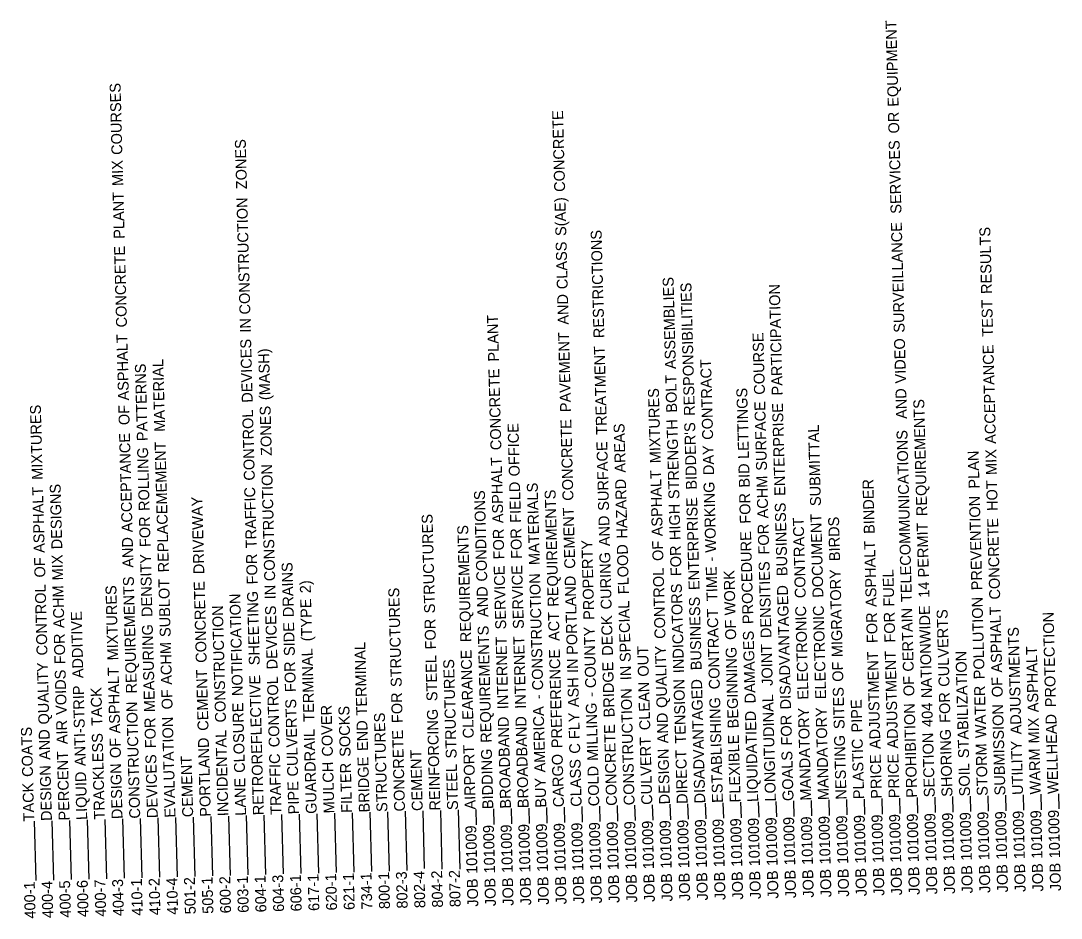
# Model space of a CAD drawing. Extents: x 1929542 to 1931706, y 595440 to 597808.
# Drawn here: x 1931132 to 1931706, y 596433 to 596929 of the extents above; entities that cross this region are included whole.
import ezdxf

# ---------------------------------------------------------------- set-up
doc = ezdxf.new("R2010")
doc.units = 0
doc.layers.add('Default', color=7, linetype='Continuous')

msp = doc.modelspace()

# ---------------------------------------------------------------- linework, layer by layer
at = {"layer": 'Default'}
for p, q in [((1931626.3, 596499.8), (1931626.52, 596491.27)), ((1931636.04, 596500.06), (1931636.27, 596491.53)), ((1931645.79, 596500.33), (1931646.02, 596491.79)), ((1931655.53, 596500.59), (1931655.76, 596492.05)), ((1931665.28, 596500.85), (1931665.51, 596492.31)), ((1931675.03, 596501.11), (1931675.26, 596492.57)), ((1931684.77, 596501.37), (1931685, 596492.84)), ((1931694.52, 596501.63), (1931694.75, 596493.1)), ((1931704.27, 596501.9), (1931704.49, 596493.63)), ((1931411.87, 596494.05), (1931412.1, 596485.51)), ((1931421.62, 596494.31), (1931421.85, 596485.77)), ((1931431.37, 596494.57), (1931431.59, 596486.03)), ((1931441.11, 596494.83), (1931441.34, 596486.29)), ((1931450.86, 596495.09), (1931451.09, 596486.56)), ((1931460.61, 596495.36), (1931460.83, 596486.82)), ((1931470.35, 596495.62), (1931470.58, 596487.08)), ((1931480.1, 596495.88), (1931480.33, 596487.34)), ((1931489.84, 596496.14), (1931490.07, 596487.6)), ((1931499.59, 596496.4), (1931499.82, 596487.86)), ((1931509.34, 596496.66), (1931509.57, 596488.13)), ((1931519.08, 596496.93), (1931519.31, 596488.39)), ((1931528.83, 596497.19), (1931529.06, 596488.65)), ((1931538.58, 596497.45), (1931538.81, 596488.91)), ((1931548.32, 596497.71), (1931548.55, 596489.17)), ((1931558.07, 596497.97), (1931558.3, 596489.43)), ((1931567.82, 596498.23), (1931568.05, 596489.7)), ((1931577.56, 596498.5), (1931577.79, 596489.96)), ((1931587.31, 596498.76), (1931587.54, 596490.22)), ((1931597.06, 596499.02), (1931597.29, 596490.48)), ((1931606.8, 596499.28), (1931607.03, 596490.74)), ((1931616.55, 596499.54), (1931616.78, 596491)), ((1931197.45, 596488.29), (1931198.33, 596455.55)), ((1931207.2, 596488.55), (1931208.08, 596455.81)), ((1931216.94, 596488.81), (1931217.82, 596456.07)), ((1931226.69, 596489.08), (1931227.57, 596456.33)), ((1931236.44, 596489.34), (1931237.31, 596456.59)), ((1931246.18, 596489.6), (1931247.06, 596456.86)), ((1931255.93, 596489.86), (1931256.81, 596457.12)), ((1931265.68, 596490.12), (1931266.55, 596457.38)), ((1931275.42, 596490.38), (1931276.3, 596457.64)), ((1931285.17, 596490.65), (1931286.05, 596457.9)), ((1931294.91, 596490.91), (1931295.79, 596458.16)), ((1931304.66, 596491.17), (1931305.54, 596458.43)), ((1931314.41, 596491.43), (1931315.29, 596458.69)), ((1931324.15, 596491.69), (1931325.03, 596458.95)), ((1931333.9, 596491.95), (1931334.78, 596459.21)), ((1931343.65, 596492.22), (1931344.53, 596459.47)), ((1931353.39, 596492.48), (1931354.25, 596460.68)), ((1931363.14, 596492.74), (1931364.01, 596460.25)), ((1931372.89, 596493), (1931373.77, 596460.26)), ((1931382.63, 596493.26), (1931382.86, 596484.72)), ((1931392.38, 596493.52), (1931392.61, 596484.99)), ((1931402.13, 596493.79), (1931402.36, 596485.25)), ((1931138.97, 596486.72), (1931139.85, 596453.98)), ((1931148.72, 596486.98), (1931149.6, 596454.24)), ((1931158.46, 596487.24), (1931159.34, 596454.5)), ((1931168.21, 596487.51), (1931169.09, 596454.76)), ((1931177.96, 596487.77), (1931178.84, 596455.02)), ((1931187.7, 596488.03), (1931188.58, 596455.29))]:
    msp.add_line(p, q, dxfattribs=at)

# ---------------------------------------------------------------- texts
for s, p in [(' EQUIPMENT', (1931616.12, 596879.03)), (' COURSES', (1931187.67, 596852.45)), (' CONCRETE', (1931432.06, 596832.02)), (' OR', (1931616.51, 596864.25)), (' ZONES', (1931256.46, 596833.49)), (' SERVICES', (1931617.7, 596819.97)), (' MIX', (1931188.14, 596835.28)), (' PLANT', (1931188.92, 596806.11)), (' CONSTRUCTION', (1931258.31, 596764.34)), (' S(AE)', (1931432.71, 596807.65)), (' SURVEILLANCE', (1931619.46, 596754.28)), (' RESTRICTIONS', (1931453.73, 596751.29)), (' RESULTS', (1931667.66, 596775.66)), (' CONCRETE', (1931190.23, 596757.2)), (' CLASS', (1931433.5, 596778.28)), (' ASSEMBLIES', (1931493.21, 596734.2)), (' RESPONSIBILITIES', (1931503.65, 596708.4)), (' PARTICIPATION', (1931552.12, 596719.63)), (' AND', (1931434.03, 596758.7)), (' TEST', (1931668.29, 596752.08)), (' IN', (1931258.58, 596754.32)), (' PLANT', (1931395.56, 596738.34)), (' ASPHALT', (1931191.31, 596716.85)), (' DEVICES', (1931259.62, 596715.64)), (' PAVEMENT', (1931435.32, 596710.43)), (' COURSE', (1931542.35, 596720.05)), (' VIDEO', (1931620.22, 596726.25)), (' (MASH)', (1931269.34, 596717.06)), (' TREATMENT', (1931455.17, 596697.91)), (' ACCEPTANCE', (1931669.88, 596692.91)), (' MATERIAL', (1931211.28, 596699.59)), (' CONTRACT', (1931513.76, 596695.15)), (' PATTERNS', (1931201.67, 596694.45)), (' CONCRETE', (1931396.87, 596689.43)), (' BOLT', (1931493.85, 596710.15)), (' MIXTURES', (1931484.85, 596682.22)), (' LETTINGS', (1931533.55, 596684.61)), (' AND', (1931620.74, 596706.67)), (' SURFACE', (1931543.48, 596678.12)), (' REQUIREMENTS', (1931631.94, 596653.01)), (' MIXTURES', (1931143.72, 596673.07)), (' OF', (1931191.68, 596703.27)), (' CONTROL', (1931260.78, 596672.63)), (' ZONES', (1931270.16, 596686.3)), (' ENTERPRISE', (1931553.61, 596664.19)), (' CONCRETE', (1931436.64, 596661.52)), (' STRENGTH', (1931495.13, 596662.4)), (" BIDDER'S", (1931504.75, 596667.65)), (' ACCEPTANCE', (1931193.27, 596644.1)), (' OFFICE', (1931407.02, 596674.97)), (' AREAS', (1931465.48, 596676.98)), (' SUBMITTAL', (1931573.27, 596658.57)), (' TELECOMMUNICATIONS', (1931623.46, 596605.61)), (' REPLACEMEMENT', (1931213.37, 596621.99)), (' SURFACE', (1931456.29, 596655.98)), (' ROLLING', (1931202.71, 596655.87)), (' DAY', (1931514.29, 596675.65)), (' PLAN', (1931660.79, 596668.23)), (' MIX', (1931670.34, 596675.74)), (' ASPHALT', (1931397.96, 596649.08)), (' BID', (1931533.98, 596668.76)), (' CONSTRUCTION', (1931272.02, 596617.14)), (' ASPHALT', (1931485.93, 596641.87)), (' DESIGNS', (1931154.5, 596634.73)), (' FIELD', (1931407.7, 596649.34)), (' MATERIALS', (1931418.08, 596626.01)), (' HAZARD', (1931466.46, 596640.64)), (' WORKING', (1931515.43, 596632.88)), (' ACHM', (1931544.19, 596651.75)), (' BINDER', (1931602.94, 596643.21)), (' HOT', (1931670.87, 596655.89)), (' ASPHALT', (1931144.81, 596632.71)), (' TRAFFIC', (1931261.78, 596635.25)), (' CONDITIONS', (1931389.07, 596616.9)), (' REQUIREMENTS', (1931428.45, 596603.02)), (' FOR', (1931534.51, 596648.86)), (' DRIVEWAY', (1931232.9, 596620.98)), (' HIGH', (1931495.74, 596639.8)), (' ENTERPRISE', (1931506.24, 596612.21)), (' BUSINESS', (1931554.8, 596619.92)), (' PREVENTION', (1931662.3, 596612.1)), (' FOR', (1931203.24, 596635.96)), (' STRUCTURES', (1931360.28, 596599.37)), (' CEMENT', (1931437.65, 596623.98)), (' AND', (1931456.82, 596636.41)), (' DOCUMENT', (1931574.62, 596607.99)), (' REQUIREMENTS', (1931380.21, 596583.46)), (' FOR', (1931544.72, 596631.84)), (' CONTRACT', (1931564.88, 596607.73)), (' BIRDS', (1931583.83, 596628.19)), (' PERMIT', (1931632.84, 596619.19)), (' CONCRETE', (1931672.19, 596606.98)), (' AND', (1931193.79, 596624.53)), (' FOR', (1931398.49, 596629.17)), (' FOR', (1931408.24, 596629.43)), (' PROCEDURE', (1931536, 596593.42)), (' PROPERTY', (1931448.16, 596595.76)), (' FLOOD', (1931467.28, 596609.9)), (' OF', (1931486.3, 596628.29)), (' FOR', (1931496.28, 596619.9)), (' ASPHALT', (1931604.02, 596602.85)), (' OF', (1931145.17, 596619.13)), (' MIX', (1931154.97, 596617.56)), (' DENSITY', (1931204.28, 596597.37)), (' FOR', (1931262.31, 596615.35)), (' CURING', (1931457.75, 596601.55)), (' -', (1931515.56, 596628.03)), (' DRAINS', (1931282.31, 596597.24)), (' SERVICE', (1931399.53, 596590.5)), (' SERVICE', (1931409.28, 596590.76)), (' CONTROL', (1931487.45, 596585.29)), (' TIME', (1931516.15, 596606.13)), (' DENSITIES', (1931545.96, 596585.71)), (' REQUIREMENTS', (1931195.66, 596555.12)), (' SUBLOT', (1931214.33, 596586.3)), (' CONSTRUCTION', (1931419.94, 596556.86)), (' PORTLAND', (1931438.92, 596576.46)), (' WORK', (1931526.12, 596598.28)), (' MIGRATORY', (1931585.26, 596575.17)), (' FUEL', (1931613.77, 596603.11)), (' CONTROL', (1931146.32, 596576.13)), (' ACHM', (1931155.67, 596591.18)), (' MIXTURES', (1931185.41, 596573.41)), (' CONCRETE', (1931234.21, 596572.07)), (' IN', (1931272.29, 596607.12)), (' 2)', (1931291.71, 596610.47)), (' STRUCTURES', (1931341.86, 596558.7)), (' AND', (1931389.59, 596597.33)), (' INDICATORS', (1931497.71, 596566.32)), (' DISADVANTAGED', (1931556.77, 596546.32)), (' 14', (1931633.15, 596607.95)), (' NOTIFICATION', (1931254.22, 596553.7)), (' SHEETING', (1931263.51, 596570.71)), (' (TYPE', (1931292.42, 596583.91)), (' BUSINESS', (1931507.42, 596567.94)), (' POLLUTION', (1931663.61, 596562.96)), (' CONSTRUCTION', (1931244.85, 596539.13)), (' DEVICES', (1931273.33, 596568.44)), (' SPECIAL', (1931468.29, 596572.46)), (' CONTRACT', (1931517.46, 596557.41)), (' ELECTRONIC', (1931566.38, 596551.72)), (' ELECTRONIC', (1931576.13, 596551.98)), (' CERTAIN', (1931624.49, 596567.18)), (' NATIONWIDE', (1931634.63, 596552.53)), (' CULVERTS', (1931644.22, 596558.82)), (' ASPHALT', (1931673.27, 596566.63)), (' ADDITIVE', (1931166.17, 596563.52)), (' FOR', (1931360.81, 596579.46)), (' ACT', (1931428.96, 596584.09)), (' DECK', (1931458.44, 596575.95)), (' OF', (1931526.48, 596584.7)), (' FOR', (1931604.56, 596582.95)), (' FOR', (1931614.3, 596583.21)), (' PROTECTION', (1931703.04, 596547.55)), (' MEASURING', (1931205.69, 596544.81)), (' SIDE', (1931282.88, 596575.8)), (' REQUIREMENTS', (1931391.46, 596527.92)), (' COUNTY', (1931449.17, 596558.11)), (' DAMAGES', (1931537.18, 596549.62)), (' ADJUSTMENTS', (1931683.94, 596532.51)), (' FOR', (1931156.21, 596571.28)), (' INTERNET', (1931400.71, 596546.43)), (' INTERNET', (1931410.46, 596546.69)), (' ACHM', (1931215.03, 596559.92)), (' TERMINAL', (1931293.61, 596539.51)), (' TERMINAL', (1931322.78, 596542.95)), (' CLEARANCE', (1931381.64, 596530.35)), (' PREFERENCE', (1931430.55, 596524.93)), (' OUT', (1931478.26, 596564.42)), (' QUALITY', (1931488.47, 596547.16)), (' BEGINNING', (1931527.79, 596535.87)), (' JOINT', (1931546.67, 596559.34)), (' ADJUSTMENT', (1931606.13, 596524.45)), (' ADJUSTMENT', (1931615.87, 596524.71)), (' STABILIZATION', (1931655.03, 596519.39)), (' ASPHALT', (1931693.36, 596544.71)), (' FOR', (1931283.42, 596555.9)), (' STEEL', (1931361.58, 596550.88)), (' STRUCTURES', (1931372.18, 596519.26)), (' IN', (1931439.19, 596566.44)), (' BRIDGE', (1931459.35, 596541.94)), (' OF', (1931585.62, 596561.59)), (' QUALITY', (1931147.35, 596538.01)), (' VOIDS', (1931156.96, 596543.31)), (' ASPHALT', (1931186.49, 596533.06)), (' CEMENT', (1931235.22, 596534.53)), (' IN', (1931468.56, 596562.44)), ('RETROREFLECTIVE', (1931265.68, 596490.12)), (' CONTROL', (1931274.48, 596525.43)), (' ASH', (1931439.7, 596547.56)), (' CLEAN', (1931479.05, 596534.83)), (' TENSION', (1931498.76, 596527.43)), ('DISADVANTAGED', (1931509.34, 596496.66)), (' OF', (1931624.85, 596553.6)), (' OF', (1931673.63, 596553.05)), (' ANTI-STRIP', (1931167.47, 596514.99)), (' TACK', (1931176.63, 596537.17)), (' OF', (1931215.4, 596546.34)), (' FOR', (1931342.4, 596538.8)), (' -', (1931449.3, 596553.25)), ('CONSTRUCTION', (1931470.35, 596495.62)), (' SITES', (1931586.32, 596535.48)), (' FOR', (1931644.75, 596538.91)), (' WATER', (1931664.49, 596530.48)), ('CONSTRUCTION', (1931197.45, 596488.29)), (' CLOSURE', (1931255.35, 596511.31)), (' CULVERTS', (1931284.67, 596509.3)), (' -', (1931420.07, 596552.01)), (' MILLING', (1931450.25, 596517.93)), ('ESTABLISHING', (1931519.08, 596496.93)), ('LONGITUDINAL', (1931548.32, 596497.71)), (' PIPE', (1931596.13, 596533.62)), ('PROHIBITION', (1931626.3, 596499.8)), (' 404', (1931635.06, 596536.63)), (' COVER', (1931303.88, 596520.29)), (' SOCKS', (1931313.64, 596520.19)), ('STRUCTURES', (1931333.9, 596491.95)), ('REINFORCING', (1931363.14, 596492.74)), (' AMERICA', (1931421.16, 596511.48)), (' FLY', (1931440.17, 596529.92)), (' AND', (1931489, 596527.59)), ('LIQUIDATIED', (1931538.58, 596497.45)), ('MANDATORY', (1931567.82, 596498.23)), ('MANDATORY', (1931577.56, 596498.5)), ('SUBMISSION', (1931675.03, 596501.11)), ('WELLHEAD', (1931704.27, 596501.9)), (' AIR', (1931157.39, 596527.13)), (' FOR', (1931206.22, 596524.91)), ('EVALUTATION', (1931216.94, 596488.81)), (' END', (1931323.3, 596523.38)), ('BROADBAND', (1931402.13, 596493.79)), ('BROADBAND', (1931411.87, 596494.05)), ('CONCRETE', (1931460.61, 596495.36)), (' FOR', (1931557.31, 596526.41)), (' MIX', (1931693.83, 596527.54)), (' COATS', (1931138.37, 596509.06)), (' AND', (1931147.87, 596518.43)), ('TRACKLESS', (1931177.96, 596487.77)), ('INCIDENTAL', (1931246.18, 596489.6)), ('GUARDRAIL', (1931294.91, 596490.91)), ('CONCRETE', (1931343.65, 596492.22)), ('FLEXIBLE', (1931528.83, 596497.19)), ('SECTION', (1931636.04, 596500.06)), ('SHORING', (1931645.79, 596500.33)), (' OF', (1931186.86, 596519.48)), ('PORTLAND', (1931236.44, 596489.34)), ('AIRPORT', (1931382.63, 596493.26)), (' C', (1931440.39, 596521.88)), ('CULVERT', (1931480.1, 596495.88)), ('NESTING', (1931587.31, 596498.76)), ('PLASTIC', (1931597.06, 596499.02)), ('STORM', (1931665.28, 596500.85)), ('UTILITY', (1931684.77, 596501.37)), ('PERCENT', (1931158.46, 596487.24)), ('DEVICES', (1931207.2, 596488.55)), ('CEMENT', (1931226.69, 596489.08)), ('TRAFFIC', (1931275.42, 596490.38)), ('CEMENT', (1931353.39, 596492.48)), ('BIDDING', (1931392.38, 596493.52)), ('CARGO', (1931431.37, 596494.57)), ('DESIGN', (1931489.84, 596496.14)), ('DIRECT', (1931499.59, 596496.4)), ('GOALS', (1931558.07, 596497.97)), ('PRICE', (1931606.8, 596499.28)), ('PRICE', (1931616.55, 596499.54)), ('WARM', (1931694.52, 596501.63)), ('DESIGN', (1931148.72, 596486.98)), ('DESIGN', (1931187.7, 596488.03)), ('MULCH', (1931304.66, 596491.17)), ('FILTER', (1931314.41, 596491.43)), ('BRIDGE', (1931324.15, 596491.69)), ('STEEL', (1931372.89, 596493)), ('CLASS', (1931441.11, 596494.83)), ('COLD', (1931450.86, 596495.09)), ('SOIL', (1931655.53, 596500.59)), ('LIQUID', (1931168.21, 596487.51)), ('TACK', (1931138.97, 596486.72)), ('LANE', (1931255.93, 596489.86)), ('PIPE', (1931285.17, 596490.65)), ('BUY', (1931421.62, 596494.31)), (' 101009', (1931539.59, 596459.7)), (' 101009', (1931549.34, 596459.96)), (' 101009', (1931559.08, 596460.22)), (' 101009', (1931568.83, 596460.48)), (' 101009', (1931578.58, 596460.74)), (' 101009', (1931588.32, 596461.01)), (' 101009', (1931598.07, 596461.27)), (' 101009', (1931607.82, 596461.53)), (' 101009', (1931617.56, 596461.79)), (' 101009', (1931627.31, 596462.05)), (' 101009', (1931637.06, 596462.31)), (' 101009', (1931646.8, 596462.57)), (' 101009', (1931656.55, 596462.84)), (' 101009', (1931666.29, 596463.1)), (' 101009', (1931676.04, 596463.36)), (' 101009', (1931685.79, 596463.62)), (' 101009', (1931695.53, 596463.88)), (' 101009', (1931705.28, 596464.14)), (' 101009', (1931383.65, 596455.51)), (' 101009', (1931393.39, 596455.77)), (' 101009', (1931403.14, 596456.03)), (' 101009', (1931412.89, 596456.3)), (' 101009', (1931422.63, 596456.56)), (' 101009', (1931432.38, 596456.82)), (' 101009', (1931442.13, 596457.08)), (' 101009', (1931451.87, 596457.34)), (' 101009', (1931461.62, 596457.6)), (' 101009', (1931471.37, 596457.87)), (' 101009', (1931481.11, 596458.13)), (' 101009', (1931490.86, 596458.39)), (' 101009', (1931500.6, 596458.65)), (' 101009', (1931510.35, 596458.91)), (' 101009', (1931520.1, 596459.17)), (' 101009', (1931529.84, 596459.44)), ('807-2', (1931374.33, 596439.4)), ('JOB', (1931559.51, 596444.37)), ('JOB', (1931569.26, 596444.63)), ('JOB', (1931579, 596444.89)), ('JOB', (1931588.75, 596445.15)), ('JOB', (1931598.49, 596445.41)), ('JOB', (1931608.24, 596445.67)), ('JOB', (1931617.99, 596445.94)), ('JOB', (1931627.73, 596446.2)), ('JOB', (1931637.48, 596446.46)), ('JOB', (1931647.23, 596446.72)), ('JOB', (1931656.97, 596446.98)), ('JOB', (1931666.72, 596447.24)), ('JOB', (1931676.47, 596447.51)), ('JOB', (1931686.21, 596447.77)), ('JOB', (1931695.96, 596448.03)), ('JOB', (1931705.71, 596448.29)), ('400-5', (1931159.23, 596433.62)), ('400-6', (1931168.97, 596433.88)), ('400-7', (1931178.72, 596434.14)), ('404-3', (1931188.47, 596434.41)), ('410-1', (1931198.89, 596434.69)), ('410-2', (1931208.64, 596434.95)), ('410-4', (1931218.38, 596435.21)), ('501-2', (1931228.13, 596435.47)), ('505-1', (1931237.87, 596435.73)), ('600-2', (1931247.62, 596435.99)), ('603-1', (1931257.37, 596436.26)), ('604-1', (1931267.11, 596436.52)), ('604-3', (1931276.86, 596436.78)), ('606-1', (1931286.61, 596437.04)), ('617-1', (1931296.35, 596437.3)), ('620-1', (1931306.1, 596437.56)), ('621-1', (1931315.85, 596437.83)), ('734-1', (1931325.59, 596438.09)), ('800-1', (1931335.34, 596438.35)), ('802-3', (1931345.09, 596438.61)), ('802-4', (1931354.83, 596438.87)), ('804-2', (1931364.58, 596439.13)), ('JOB', (1931384.07, 596439.66)), ('JOB', (1931393.82, 596439.92)), ('JOB', (1931403.57, 596440.18)), ('JOB', (1931413.31, 596440.44)), ('JOB', (1931423.06, 596440.7)), ('JOB', (1931432.8, 596440.96)), ('JOB', (1931442.55, 596441.23)), ('JOB', (1931452.3, 596441.49)), ('JOB', (1931462.04, 596441.75)), ('JOB', (1931471.79, 596442.01)), ('JOB', (1931481.54, 596442.27)), ('JOB', (1931491.28, 596442.53)), ('JOB', (1931501.03, 596442.8)), ('JOB', (1931510.78, 596443.06)), ('JOB', (1931520.52, 596443.32)), ('JOB', (1931530.27, 596443.58)), ('JOB', (1931540.02, 596443.84)), ('JOB', (1931549.76, 596444.1)), ('400-1', (1931139.74, 596433.1)), ('400-4', (1931149.48, 596433.36))]:
    msp.add_text(s, height=6, rotation=91.53769, dxfattribs=at).set_placement(p)

doc.saveas('drawing.dxf')
